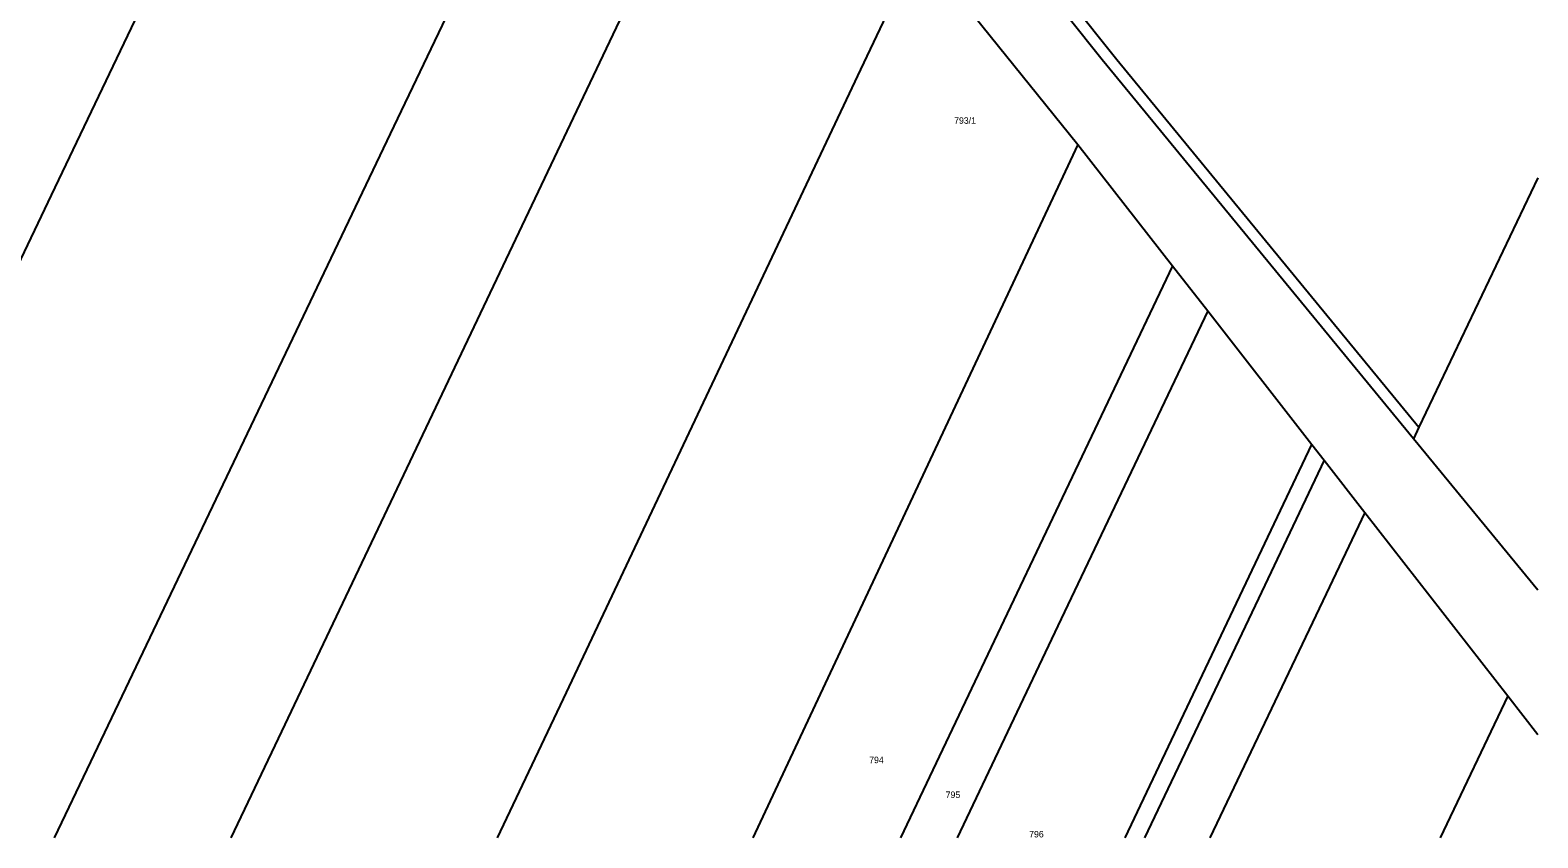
# Model space of a CAD drawing. Extents: x -504601 to -503665, y -1079870 to -1078626.
# Drawn here: x -504059.2 to -503665.3, y -1079869.8 to -1079659 of the extents above; entities that cross this region are included whole.
import ezdxf

# ---------------------------------------------------------------- set-up
doc = ezdxf.new("R2010")
doc.units = 0
doc.layers.add('Hranice parcel', color=7, linetype='Continuous')
doc.layers.add('Parcelní čísla', color=7, linetype='Continuous')

msp = doc.modelspace()

# ---------------------------------------------------------------- linework, layer by layer
at = {"layer": 'Hranice parcel'}
for p, q in [((-503827.05, -1079637.31), (-503785.46, -1079688.81)), ((-503785.46, -1079688.81), (-503760.75, -1079720.48)), ((-503665.31, -1079697.5), (-503696.41, -1079762.65)), ((-503760.75, -1079720.48), (-503751.56, -1079732.27)), ((-503751.56, -1079732.27), (-503724.33, -1079767.18)), ((-503696.41, -1079762.65), (-503697.84, -1079765.64)), ((-503724.33, -1079767.18), (-503721.15, -1079771.25)), ((-503665.31, -1079805.18), (-503697.84, -1079765.64)), ((-503721.15, -1079771.25), (-503710.52, -1079784.89)), ((-503710.52, -1079784.89), (-503673.14, -1079832.8)), ((-503673.14, -1079832.8), (-503690.85, -1079869.85))]:
    msp.add_line(p, q, dxfattribs=at)
for points in [[(-503697.84, -1079765.64), (-503779.17, -1079666.7), (-503806.76, -1079632.06), (-503843.08, -1079586.46), (-503955.21, -1079445.68)], [(-504133.72, -1079869.85), (-504130.18, -1079862.44), (-504053.56, -1079702.06), (-503975.76, -1079539.21), (-503950.22, -1079485.75)], [(-504052.8, -1079869.85), (-504043.32, -1079850.01), (-503965, -1079686.08), (-503899.25, -1079548.46)], [(-504006.66, -1079869.85), (-503993.46, -1079842.09), (-503916.36, -1079680.01), (-503870.57, -1079583.75)], [(-503824.73, -1079604.69), (-503775.32, -1079666.65), (-503696.41, -1079762.65)], [(-503937.05, -1079869.85), (-503919.87, -1079833.53), (-503842.14, -1079669.21), (-503827.05, -1079637.31)], [(-503785.46, -1079688.81), (-503847.54, -1079821.2), (-503870.35, -1079869.85)], [(-503760.75, -1079720.48), (-503806.47, -1079816.61), (-503831.79, -1079869.85)], [(-503751.56, -1079732.27), (-503790.67, -1079814.5), (-503817, -1079869.85)], [(-503773.16, -1079869.85), (-503744.82, -1079810.26), (-503724.33, -1079767.18)], [(-503721.15, -1079771.25), (-503738.33, -1079807.37), (-503768.05, -1079869.85)], [(-503710.52, -1079784.89), (-503720.64, -1079806.13), (-503751, -1079869.85)], [(-503673.14, -1079832.8), (-503665.31, -1079842.84)]]:
    msp.add_lwpolyline(points, dxfattribs=at)

# ---------------------------------------------------------------- texts
at = {"layer": 'Parcelní čísla'}
for s, p in [('793/1', (-503817.79, -1079683.42)), ('794', (-503839.99, -1079850.36)), ('795', (-503820, -1079859.45)), ('796', (-503798.2, -1079869.75))]:
    msp.add_text(s, height=1.7, dxfattribs=at).set_placement(p)

doc.saveas('drawing.dxf')
